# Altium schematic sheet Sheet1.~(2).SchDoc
size B; SheetNumber: 1; SheetTotal: 1; SPICEModelCacheKHWKRCUS: <root> / <DocumentId>KHWKRCUS</DocumentId> / <CacheFrame Number="0"> / <Model Name="nmos" Kind="MDL"> / <Text>*Default N-Channel MOSFET / *Pinout: D,G,S / .MODEL NMOS NMOS()</Text> / </Model> / <Model Name="diode" Kind="MDL"> / <Text>*Default Diode / *Diode Pinout: A,K / .MODEL DIODE D()</Text> / </Model> / </CacheFrame> / </root>
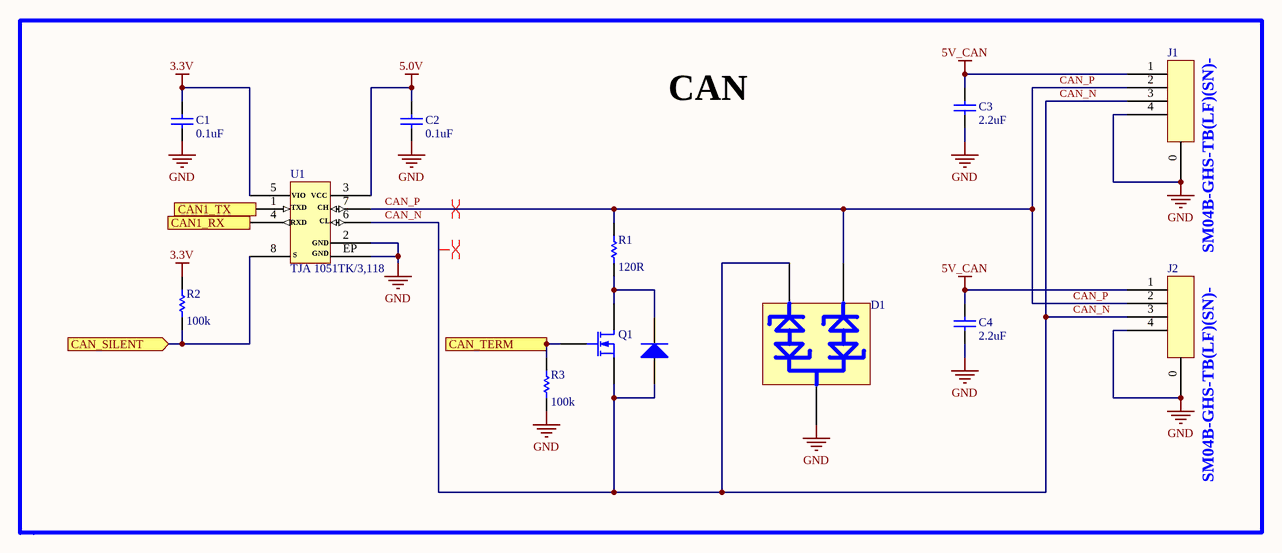
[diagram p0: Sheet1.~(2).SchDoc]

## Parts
C1  0.1uF  [RAD-0.3]
C2  0.1uF  [RAD-0.3]
C3  2.2uF  [RAD-0.3]
C4  2.2uF  [RAD-0.3]
D1  BRIDGE  (value not drawn)
D?  Diode  [SMC]  (value not drawn)
J1  HEADER  (value not drawn)
J2  HEADER  (value not drawn)
Q1  MOSFET-N  [E3]  (value not drawn)
R1  120R  [AXIAL-0.3]
R2  100k  [AXIAL-0.3]
R3  100k  [AXIAL-0.3]
U1  TJA 1051TK/3,118

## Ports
CAN1_RX (out), CAN1_TX (in), CAN_SILENT (in), CAN_TERM (in)

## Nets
3.3V: C1.2 R2.2 U1.5
5.0V: C2.2 U1.3
5V_CAN: C3.2 C4.2 J1.1 J2.1
GND: C1.1 C2.1 C3.1 C4.1 D1.3 J1.0 J1.4 J2.0 J2.4 R3.1 U1.2 U1.EP
CAN1_RX: U1.4 ; port CAN1_RX
CAN_N: D1.2 D?.1(A) J1.3 J2.3 Q1.3(S) U1.6
CAN_P: D1.1 J1.2 J2.2 R1.2 U1.7
CAN_SILENT: R2.1 U1.8 ; port CAN_SILENT
CAN_TERM: Q1.2(G) R3.2 ; port CAN_TERM
NetD?_2: D?.2(K) Q1.1(D) R1.1

Not connected (* = marked no-connect by the designer): U1 1

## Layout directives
differential pair: CAN_N, CAN_P

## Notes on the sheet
- CAN
- (near J1) SM04B-GHS-TB(LF)(SN)-
- (near J2) SM04B-GHS-TB(LF)(SN)-

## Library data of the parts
C1-C4 = Cap: Capacitor
D? = Diode: Default Diode
Q1 = MOSFET-N: N-Channel MOSFET
R1-R3 = Res1: Resistor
